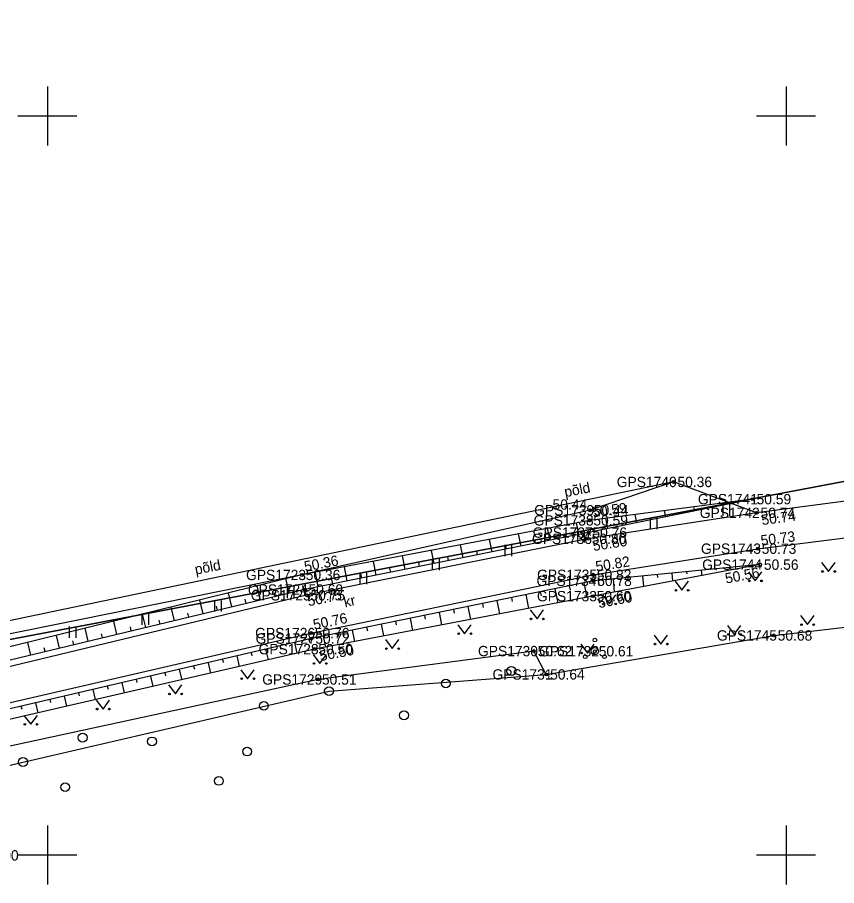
# Model space of a CAD drawing. Extents: x 551623 to 559850, y 6561220 to 6567135.
# Drawn here: x 556248 to 556303.4, y 6565297.9 to 6565356.7 of the extents above; entities that cross this region are included whole.
import ezdxf

# ---------------------------------------------------------------- set-up
doc = ezdxf.new("R2010")
doc.units = 0
for name, color, linetype in [('HALJASTUS', 7, 'Continuous'), ('KORGUS-EH2000', 7, 'Continuous'), ('MOOTKORG-EH2000', 7, 'Continuous'), ('MOOTMPUNKT', 7, 'Continuous'), ('MOOTNR', 7, 'Continuous'), ('MOOTPIIR', 7, 'Continuous'), ('PIIR', 7, 'Continuous'), ('PUU', 7, 'Continuous'), ('RELJEEF', 7, 'Continuous'), ('TEE', 7, 'Continuous'), ('VORK', 7, 'Continuous')]:
    doc.layers.add(name, color=color, linetype=linetype)

msp = doc.modelspace()

# ---------------------------------------------------------------- linework, layer by layer
at = {"layer": 'HALJASTUS'}
for p, q in [((556295.711, 6565323.706), (556295.711, 6565322.945)), ((556296.166, 6565323.706), (556296.166, 6565322.945)), ((556290.792, 6565322.809), (556290.792, 6565322.048)), ((556291.247, 6565322.809), (556291.247, 6565322.048)), ((556285.873, 6565321.912), (556285.873, 6565321.151)), ((556286.328, 6565321.912), (556286.328, 6565321.151)), ((556280.962, 6565320.972), (556280.962, 6565320.211)), ((556281.417, 6565320.972), (556281.417, 6565320.211)), ((556276.053, 6565320.025), (556276.053, 6565319.264)), ((556276.508, 6565320.025), (556276.508, 6565319.264)), ((556302.404, 6565319.785), (556302.868, 6565319.178)), ((556302.868, 6565319.178), (556303.313, 6565319.785)), ((556271.143, 6565319.078), (556271.143, 6565318.317)), ((556271.598, 6565319.078), (556271.598, 6565318.317)), ((556297.445, 6565319.15), (556297.908, 6565318.544)), ((556297.908, 6565318.544), (556298.354, 6565319.15)), ((556266.234, 6565318.132), (556266.234, 6565317.37)), ((556266.689, 6565318.132), (556266.689, 6565317.37)), ((556292.485, 6565318.516), (556292.949, 6565317.909)), ((556292.949, 6565317.909), (556293.394, 6565318.516)), ((556287.574, 6565317.589), (556288.038, 6565316.982)), ((556288.038, 6565316.982), (556288.483, 6565317.589)), ((556261.316, 6565317.226), (556261.316, 6565316.465)), ((556261.771, 6565317.226), (556261.771, 6565316.465)), ((556256.396, 6565316.339), (556256.396, 6565315.578)), ((556256.851, 6565316.339), (556256.851, 6565315.578)), ((556282.677, 6565316.582), (556283.14, 6565315.975)), ((556283.14, 6565315.975), (556283.586, 6565316.582)), ((556300.98, 6565316.194), (556301.443, 6565315.587)), ((556301.443, 6565315.587), (556301.889, 6565316.194)), ((556251.475, 6565315.452), (556251.475, 6565314.69)), ((556251.93, 6565315.452), (556251.93, 6565314.69)), ((556277.779, 6565315.576), (556278.242, 6565314.969)), ((556278.242, 6565314.969), (556278.688, 6565315.576)), ((556296.024, 6565315.532), (556296.487, 6565314.925)), ((556296.487, 6565314.925), (556296.933, 6565315.532)), ((556272.881, 6565314.569), (556273.345, 6565313.962)), ((556273.345, 6565313.962), (556273.79, 6565314.569)), ((556291.068, 6565314.87), (556291.531, 6565314.264)), ((556291.531, 6565314.264), (556291.977, 6565314.87)), ((556286.105, 6565314.264), (556286.568, 6565313.657)), ((556286.568, 6565313.657), (556287.014, 6565314.264)), ((556267.984, 6565313.559), (556268.448, 6565312.953)), ((556268.448, 6565312.953), (556268.893, 6565313.559)), ((556263.091, 6565312.531), (556263.555, 6565311.924)), ((556263.555, 6565311.924), (556264, 6565312.531)), ((556258.198, 6565311.502), (556258.662, 6565310.896)), ((556258.662, 6565310.896), (556259.107, 6565311.502)), ((556253.305, 6565310.474), (556253.769, 6565309.867)), ((556253.769, 6565309.867), (556254.214, 6565310.474)), ((556248.412, 6565309.446), (556248.875, 6565308.839)), ((556248.875, 6565308.839), (556249.321, 6565309.446))]:
    msp.add_line(p, q, dxfattribs=at)
for points in [[(556292.386, 6565325.238), (556286.728, 6565323.326), (556267.227, 6565318.945), (556244.568, 6565314.375), (556233.701, 6565312.976)], [(556283.768, 6565312.214), (556282.924, 6565313.794), (556268.321, 6565311.876), (556245.361, 6565306.917), (556234.601, 6565304.511), (556225.246, 6565301.174), (556225.084, 6565299.935)]]:
    msp.add_lwpolyline(points, dxfattribs=at)
for centre, radius in [((556302.467, 6565319.178), 0.055), ((556303.295, 6565319.178), 0.055), ((556297.507, 6565318.544), 0.055), ((556298.336, 6565318.544), 0.055), ((556292.548, 6565317.909), 0.055), ((556293.376, 6565317.909), 0.055), ((556287.637, 6565316.982), 0.055), ((556288.465, 6565316.982), 0.055), ((556282.739, 6565315.975), 0.055), ((556283.568, 6565315.975), 0.055), ((556301.042, 6565315.587), 0.055), ((556301.871, 6565315.587), 0.055), ((556277.841, 6565314.969), 0.055), ((556278.67, 6565314.969), 0.055), ((556296.086, 6565314.925), 0.055), ((556296.915, 6565314.925), 0.055), ((556272.944, 6565313.962), 0.055), ((556273.773, 6565313.962), 0.055), ((556291.13, 6565314.264), 0.055), ((556291.959, 6565314.264), 0.055), ((556286.167, 6565313.657), 0.055), ((556286.996, 6565313.657), 0.055), ((556268.047, 6565312.953), 0.055), ((556268.876, 6565312.953), 0.055), ((556281.406, 6565312.45), 0.3), ((556263.154, 6565311.924), 0.055), ((556263.982, 6565311.924), 0.055), ((556276.97, 6565311.6), 0.3), ((556269.066, 6565311.081), 0.3), ((556258.261, 6565310.896), 0.055), ((556259.089, 6565310.896), 0.055), ((556264.653, 6565310.089), 0.3), ((556253.368, 6565309.867), 0.055), ((556254.196, 6565309.867), 0.055), ((556274.139, 6565309.451), 0.3), ((556248.474, 6565308.839), 0.055), ((556249.303, 6565308.839), 0.055), ((556252.383, 6565307.94), 0.3), ((556257.079, 6565307.681), 0.3), ((556263.521, 6565306.996), 0.3), ((556248.349, 6565306.288), 0.3), ((556261.609, 6565305.013), 0.3), ((556251.204, 6565304.588), 0.3)]:
    msp.add_circle(centre, radius, dxfattribs=at)
at = {"layer": 'KORGUS-EH2000'}
for centre in [(556292.386, 6565325.238), (556286.728, 6565323.326), (556286.693, 6565322.639), (556298.007, 6565323.148), (556286.58, 6565321.39), (556298.088, 6565320.723), (556298.237, 6565319.643), (556267.227, 6565318.945), (556286.927, 6565318.955), (556267.546, 6565317.57), (556286.916, 6565317.511), (556267.841, 6565315.013), (556299.17, 6565314.853), (556268.077, 6565313.926), (556283.768, 6565312.214), (556268.321, 6565311.876)]:
    msp.add_circle(centre, 0.1, dxfattribs=at)
at = {"layer": 'MOOTMPUNKT'}
for centre in [(556292.386, 6565325.238), (556297.741, 6565324.073), (556286.728, 6565323.326), (556286.693, 6565322.639), (556298.007, 6565323.148), (556286.631, 6565321.814), (556286.58, 6565321.39), (556298.088, 6565320.723), (556298.237, 6565319.643), (556267.227, 6565318.945), (556286.927, 6565318.955), (556286.954, 6565318.548), (556267.416, 6565317.958), (556267.546, 6565317.57), (556286.916, 6565317.511), (556267.841, 6565315.013), (556267.873, 6565314.642), (556299.17, 6565314.853), (556268.077, 6565313.926), (556282.924, 6565313.794), (556287.058, 6565313.785), (556283.768, 6565312.214), (556268.321, 6565311.876)]:
    msp.add_circle(centre, 0.1, dxfattribs=at)
at = {"layer": 'MOOTPIIR'}
for points in [[(556317.29, 6565325.671), (556298.007, 6565323.148), (556292.386, 6565325.238), (556233.701, 6565312.976), (556223.169, 6565308.85), (556214.051, 6565308.489), (556203.216, 6565309.397), (556197.609, 6565310.789), (556194.429, 6565307.325), (556191.934, 6565304.799), (556191.351, 6565302.574), (556183.617, 6565304.516), (556162.392, 6565313.566), (556146.837, 6565320.486), (556131.546, 6565328.064), (556116.861, 6565334.423), (556089.682, 6565344.853), (556063.899, 6565353.523), (556057.929, 6565353.821), (556039.198, 6565356.19)], [(556319.439, 6565253.295), (556278.301, 6565271.261), (556258.766, 6565280.179), (556222.735, 6565295.867), (556225.084, 6565299.935), (556245.706, 6565305.674), (556269.066, 6565311.081), (556283.768, 6565312.214), (556299.17, 6565314.853), (556317.928, 6565317.026)]]:
    msp.add_lwpolyline(points, dxfattribs=at)
at = {"layer": 'PIIR'}
for points in [[(556340.11, 6565662.55), (556389.4, 6565609.96), (556364.34, 6565374.53), (556350.73, 6565342.07), (556335.44, 6565331.24), (556229.81, 6565311.25), (556213.87, 6565303.19), (556199.38, 6565295.85), (556122.95, 6565328.71), (556145.23, 6565518.55)], [(556217.39, 6565298.59), (556213.87, 6565303.19), (556229.81, 6565311.25), (556335.44, 6565331.24), (556350.73, 6565342.07), (556507.54, 6565334), (556519.21, 6565368.05), (556548.5, 6565368.1), (556612.15, 6565380.04), (556615.14, 6565380.2), (556613.56, 6565366.23), (556611.32, 6565356.67), (556591.74, 6565273.2), (556570.09, 6565180.67), (556561.87, 6565145.74), (556557.67, 6565147.61), (556393.49, 6565220.36)]]:
    msp.add_lwpolyline(points, close=True, dxfattribs=at)
at = {"layer": 'PUU'}
for centre, radius in [((556287.058, 6565314.535), 0.125), ((556287.058, 6565313.785), 0.25), ((556286.408, 6565313.41), 0.125), ((556287.708, 6565313.41), 0.125)]:
    msp.add_circle(centre, radius, dxfattribs=at)
at = {"layer": 'RELJEEF'}
for p, q in [((556291.861, 6565322.877), (556291.775, 6565323.299)), ((556293.821, 6565323.276), (556293.764, 6565323.557)), ((556294.801, 6565323.475), (556294.788, 6565323.538)), ((556295.781, 6565323.675), (556295.752, 6565323.815)), ((556287.941, 6565322.08), (556287.799, 6565322.782)), ((556289.901, 6565322.479), (556289.787, 6565323.04)), ((556290.881, 6565322.678), (556290.851, 6565322.826)), ((556292.841, 6565323.077), (556292.82, 6565323.182)), ((556285.981, 6565321.683), (556285.823, 6565322.473)), ((556288.921, 6565322.28), (556288.883, 6565322.469)), ((556282.059, 6565320.896), (556281.892, 6565321.728)), ((556284.02, 6565321.29), (556283.857, 6565322.1)), ((556285.001, 6565321.487), (556284.952, 6565321.727)), ((556286.961, 6565321.881), (556286.914, 6565322.113)), ((556278.137, 6565320.109), (556277.962, 6565320.982)), ((556280.098, 6565320.503), (556279.927, 6565321.355)), ((556281.079, 6565320.7), (556281.028, 6565320.952)), ((556283.04, 6565321.093), (556282.99, 6565321.339)), ((556276.177, 6565319.716), (556275.997, 6565320.609)), ((556279.118, 6565320.306), (556279.066, 6565320.565)), ((556272.255, 6565318.929), (556272.067, 6565319.863)), ((556274.216, 6565319.322), (556274.032, 6565320.236)), ((556275.196, 6565319.519), (556275.142, 6565319.79)), ((556277.157, 6565319.913), (556277.104, 6565320.177)), ((556270.294, 6565318.535), (556270.102, 6565319.491)), ((556273.235, 6565319.125), (556273.18, 6565319.403)), ((556294.256, 6565319.256), (556294.291, 6565318.9)), ((556295.251, 6565319.353), (556295.259, 6565319.273)), ((556296.247, 6565319.45), (556296.264, 6565319.271)), ((556297.242, 6565319.546), (556297.245, 6565319.519)), ((556266.38, 6565317.71), (556266.149, 6565318.68)), ((556268.333, 6565318.142), (556268.137, 6565319.118)), ((556269.313, 6565318.338), (556269.255, 6565318.628)), ((556271.274, 6565318.732), (556271.217, 6565319.015)), ((556288.284, 6565318.677), (556288.371, 6565317.785)), ((556289.279, 6565318.774), (556289.303, 6565318.533)), ((556290.275, 6565318.87), (556290.344, 6565318.157)), ((556291.27, 6565318.967), (556291.288, 6565318.779)), ((556292.265, 6565319.063), (556292.317, 6565318.528)), ((556293.261, 6565319.16), (556293.274, 6565319.026)), ((556264.435, 6565317.245), (556264.206, 6565318.203)), ((556267.353, 6565317.943), (556267.283, 6565318.235)), ((556284.344, 6565318.014), (556284.54, 6565317.059)), ((556285.324, 6565318.214), (556285.384, 6565317.924)), ((556286.304, 6565318.415), (556286.505, 6565317.433)), ((556287.289, 6565318.58), (556287.317, 6565318.286)), ((556262.49, 6565316.781), (556262.264, 6565317.725)), ((556265.408, 6565317.478), (556265.339, 6565317.767)), ((556282.385, 6565317.613), (556282.575, 6565316.685)), ((556283.365, 6565317.813), (556283.423, 6565317.531)), ((556260.545, 6565316.316), (556260.322, 6565317.248)), ((556261.517, 6565316.548), (556261.45, 6565316.83)), ((556263.463, 6565317.013), (556263.394, 6565317.298)), ((556279.446, 6565317.011), (556279.5, 6565316.745)), ((556280.426, 6565317.212), (556280.61, 6565316.311)), ((556281.405, 6565317.412), (556281.461, 6565317.138)), ((556256.654, 6565315.386), (556256.438, 6565316.293)), ((556258.599, 6565315.851), (556258.38, 6565316.77)), ((556259.572, 6565316.084), (556259.506, 6565316.361)), ((556276.507, 6565316.409), (556276.68, 6565315.563)), ((556277.487, 6565316.61), (556277.539, 6565316.352)), ((556278.466, 6565316.81), (556278.645, 6565315.937)), ((556254.709, 6565314.922), (556254.495, 6565315.815)), ((556257.627, 6565315.619), (556257.561, 6565315.893)), ((556273.568, 6565315.808), (556273.617, 6565315.566)), ((556274.548, 6565316.008), (556274.715, 6565315.189)), ((556275.527, 6565316.209), (556275.578, 6565315.959)), ((556252.764, 6565314.457), (556252.553, 6565315.338)), ((556255.682, 6565315.154), (556255.617, 6565315.424)), ((556270.629, 6565315.206), (556270.785, 6565314.441)), ((556271.609, 6565315.407), (556271.656, 6565315.173)), ((556272.588, 6565315.607), (556272.75, 6565314.815)), ((556250.818, 6565313.992), (556250.611, 6565314.86)), ((556251.791, 6565314.224), (556251.728, 6565314.487)), ((556253.736, 6565314.689), (556253.673, 6565314.955)), ((556267.691, 6565314.599), (556267.741, 6565314.382)), ((556268.669, 6565314.805), (556268.82, 6565314.068)), ((556269.649, 6565315.005), (556269.695, 6565314.78)), ((556248.873, 6565313.527), (556248.669, 6565314.383)), ((556249.846, 6565313.76), (556249.784, 6565314.018)), ((556264.769, 6565313.918), (556264.936, 6565313.203)), ((556265.743, 6565314.145), (556265.793, 6565313.93)), ((556266.717, 6565314.372), (556266.885, 6565313.652)), ((556262.822, 6565313.464), (556262.987, 6565312.754)), ((556263.795, 6565313.691), (556263.845, 6565313.477)), ((556259.9, 6565312.782), (556259.949, 6565312.572)), ((556260.874, 6565313.009), (556261.038, 6565312.305)), ((556261.848, 6565313.237), (556261.897, 6565313.025)), ((556257.952, 6565312.328), (556258.001, 6565312.119)), ((556258.926, 6565312.555), (556259.089, 6565311.857)), ((556255.031, 6565311.647), (556255.191, 6565310.959)), ((556256.005, 6565311.874), (556256.053, 6565311.667)), ((556256.978, 6565312.101), (556257.14, 6565311.408)), ((556252.109, 6565310.965), (556252.157, 6565310.761)), ((556253.083, 6565311.192), (556253.242, 6565310.51)), ((556254.057, 6565311.419), (556254.105, 6565311.214)), ((556250.161, 6565310.511), (556250.208, 6565310.309)), ((556251.135, 6565310.738), (556251.293, 6565310.062)), ((556248.214, 6565310.057), (556248.26, 6565309.856)), ((556249.187, 6565310.284), (556249.344, 6565309.613))]:
    msp.add_line(p, q, dxfattribs=at)
for points in [[(556297.741, 6565324.073), (556286.631, 6565321.814), (556267.416, 6565317.958), (556244.728, 6565312.537), (556234.325, 6565309.803), (556224.619, 6565307.168)], [(556297.741, 6565324.073), (556286.693, 6565322.639), (556267.227, 6565318.945), (556244.6, 6565313.383), (556234.267, 6565310.399), (556224.619, 6565307.168)], [(556298.237, 6565319.643), (556286.954, 6565318.548), (556267.873, 6565314.642), (556245.025, 6565309.313), (556234.806, 6565306.359), (556224.967, 6565303.145), (556216.887, 6565299.924), (556215.839, 6565298.816)], [(556298.237, 6565319.643), (556286.916, 6565317.511), (556268.077, 6565313.926), (556245.054, 6565308.625), (556234.869, 6565305.826), (556224.991, 6565302.538), (556215.839, 6565298.816)]]:
    msp.add_lwpolyline(points, dxfattribs=at)
at = {"layer": 'TEE'}
for points in [[(556356.597, 6565346.303), (556351.215, 6565339.154), (556344.863, 6565333.835), (556337.149, 6565329.848), (556328.266, 6565327.228), (556317.29, 6565325.671), (556298.007, 6565323.148), (556286.58, 6565321.39), (556267.546, 6565317.57), (556244.57, 6565312.043), (556234.474, 6565309.292), (556224.053, 6565306.048), (556211.7, 6565301.845), (556209.919, 6565301.461), (556206.606, 6565301.399), (556202.993, 6565302.377), (556199.245, 6565304.369), (556194.429, 6565307.325)], [(556175.15, 6565203.291), (556172.371, 6565205.166), (556170.617, 6565207.184), (556180.061, 6565228.987), (556188.487, 6565247.314), (556199.182, 6565269.439), (556203.276, 6565278.708), (556205.245, 6565285.017), (556206.201, 6565290.125), (556208.027, 6565293.465), (556209.59, 6565295.964), (556212.519, 6565297.656), (556212.957, 6565298.286), (556224.759, 6565303.642), (556234.832, 6565306.956), (556244.933, 6565309.73), (556267.841, 6565315.013), (556286.927, 6565318.955), (556298.088, 6565320.723), (556317.752, 6565323.201)]]:
    msp.add_lwpolyline(points, dxfattribs=at)
at = {"layer": 'VORK'}
for p, q in [((556250, 6565352), (556250, 6565348)), ((556300, 6565352), (556300, 6565348)), ((556248, 6565350), (556252, 6565350)), ((556298, 6565350), (556302, 6565350)), ((556250, 6565302), (556250, 6565298)), ((556300, 6565302), (556300, 6565298)), ((556248, 6565300), (556252, 6565300)), ((556298, 6565300), (556302, 6565300))]:
    msp.add_line(p, q, dxfattribs=at)

# ---------------------------------------------------------------- texts
at = {"layer": 'HALJASTUS'}
for p in [(556285.057, 6565324.204), (556260.046, 6565318.963)]:
    msp.add_text('põld', height=0.7, rotation=11.07695, dxfattribs=at).set_placement(p)
at = {"layer": 'KORGUS-EH2000'}
for s, p in [(' 50.36', (556292.386, 6565324.889)), (' 50.44', (556283.933, 6565323.36)), (' 50.68', (556299.17, 6565314.503)), (' 50.51', (556268.321, 6565311.525)), (' 50.64', (556283.768, 6565311.864))]:
    msp.add_text(s, height=0.7, dxfattribs=at).set_placement(p)
for s, rotation, p in [(' 50.59', 7.39932, (556286.671, 6565322.812)), (' 50.74', 7.45453, (556298.12, 6565322.28)), (' 50.80', 8.74688, (556286.713, 6565320.525)), (' 50.73', 7.18375, (556298.067, 6565320.897)), (' 50.36', 10.74343, (556267.194, 6565319.117)), (' 50.82', 9.00088, (556286.9, 6565319.128)), (' 50.56', 10.66276, (556295.686, 6565318.309)), (' 50.75', 11.34686, (556267.42, 6565316.772)), (' 50.60', 10.66276, (556287.078, 6565316.651)), (' 50.76', 11.66892, (556267.806, 6565315.185)), (' 50.50', 10.7746, (556268.241, 6565313.067))]:
    msp.add_text(s, height=0.7, rotation=rotation, dxfattribs=at).set_placement(p)
at = {"layer": 'MOOTKORG-EH2000'}
for s, p in [(' 50.36', (556292.386, 6565324.889)), (' 50.59', (556297.741, 6565323.723)), (' 50.44', (556286.728, 6565322.976)), (' 50.74', (556298.007, 6565322.798)), (' 50.59', (556286.693, 6565322.289)), (' 50.76', (556286.631, 6565321.464)), (' 50.80', (556286.58, 6565321.04)), (' 50.73', (556298.088, 6565320.373)), (' 50.56', (556298.237, 6565319.293)), (' 50.36', (556267.227, 6565318.595)), (' 50.82', (556286.927, 6565318.605)), (' 50.78', (556286.954, 6565318.198)), (' 50.69', (556267.416, 6565317.608)), (' 50.75', (556267.546, 6565317.22)), (' 50.60', (556286.916, 6565317.161)), (' 50.76', (556267.841, 6565314.663)), (' 50.68', (556299.17, 6565314.503)), (' 50.72', (556267.873, 6565314.292)), (' 50.50', (556268.077, 6565313.576)), (' 50.62', (556282.924, 6565313.444)), (' 50.61', (556287.058, 6565313.435)), (' 50.51', (556268.321, 6565311.525)), (' 50.64', (556283.768, 6565311.864))]:
    msp.add_text(s, height=0.7, dxfattribs=at).set_placement(p)
at = {"layer": 'MOOTNR'}
for s, p in [('GPS1740 ', (556288.536, 6565324.889)), ('GPS1741 ', (556294.031, 6565323.723)), ('GPS1739 ', (556282.948, 6565322.976)), ('GPS1742 ', (556294.157, 6565322.798)), ('GPS1738 ', (556282.913, 6565322.289)), ('GPS1737 ', (556282.852, 6565321.464)), ('GPS1736 ', (556282.8, 6565321.04)), ('GPS1743 ', (556294.239, 6565320.373)), ('GPS1744 ', (556294.318, 6565319.293)), ('GPS1723 ', (556263.447, 6565318.595)), ('GPS1735 ', (556283.147, 6565318.605)), ('GPS1734 ', (556283.104, 6565318.198)), ('GPS1724 ', (556263.566, 6565317.608)), ('GPS1725 ', (556263.766, 6565317.22)), ('GPS1733 ', (556283.136, 6565317.161)), ('GPS1726 ', (556264.062, 6565314.663)), ('GPS1745 ', (556295.32, 6565314.503)), ('GPS1727 ', (556264.093, 6565314.292)), ('GPS1728 ', (556264.297, 6565313.576)), ('GPS1730 ', (556279.145, 6565313.444)), ('GPS1732 ', (556283.278, 6565313.435)), ('GPS1729 ', (556264.541, 6565311.525)), ('GPS1731 ', (556280.128, 6565311.864))]:
    msp.add_text(s, height=0.7, dxfattribs=at).set_placement(p)
at = {"layer": 'TEE'}
msp.add_text('kr', height=0.7, rotation=13.4277, dxfattribs=at).set_placement((556270.151, 6565316.743))
at = {"layer": 'VORK'}
msp.add_text('X = 6565300', height=0.7, dxfattribs=at).set_placement((556242.719, 6565299.621))

doc.saveas('drawing.dxf')
